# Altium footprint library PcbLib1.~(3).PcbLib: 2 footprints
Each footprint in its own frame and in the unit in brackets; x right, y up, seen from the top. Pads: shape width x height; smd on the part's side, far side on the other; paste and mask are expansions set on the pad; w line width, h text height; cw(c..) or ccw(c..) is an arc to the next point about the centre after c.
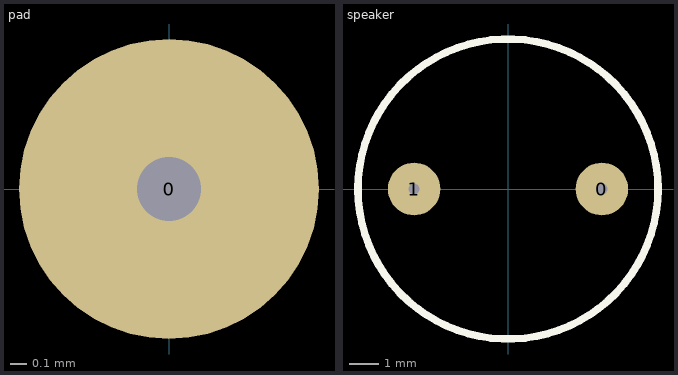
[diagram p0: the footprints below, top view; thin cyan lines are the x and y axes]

## pad [mil]
pads (1):
  round 70 hole 15: 0(0,0)

## speaker [mil]
pads (2):
  round 70 hole 15: 0(125,0) 1(-125,0)
Top Overlay:
  circle w10: c0,0 r199.62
